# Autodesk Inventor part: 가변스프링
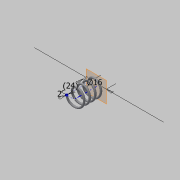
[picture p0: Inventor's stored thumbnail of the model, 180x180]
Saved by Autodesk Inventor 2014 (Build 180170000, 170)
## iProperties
Created: 2015-04
Part Number: 가변스프링
Material: Generic
Document SubType Name: Modeling
Designer: Administrator
Density: 1 g/cm^3
Appearance: Default
Author: Administrator
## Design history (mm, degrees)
sketch "스케치1"
  geometry: L1 (0, 0)-(-8, 0); L2 (-8, 0)-(-8, 11.987); L3 (-8, 11.987)-(0, 11.987); L4 (0, 11.987)-(0, 0); C1 r 1 at (-8, 0)
  constraints: 8 end point, 2 parallel, 1 centre point, 1 coincident, 1 horizontal, 1 perpendicular
  dimensions: "d0" = 16 diameter of L2 L4; "d1" = 11.987 dimension on L3 L1 (derived); "d2" = 2 diameter of C1
feature "코일1" pitch "d3" = 10; turns "d5" = 4; dims "d4" = 11.987 (= d1), "d6" = 0, angle "d7" = 90 deg, angle "d8" = 90 deg, "d9" = 0, "d10" = 0
sketch "스케치2"
  geometry: L1 (7, 0)-(9, 0) reference; 1 further point
  constraints: 1 horizontal alignment
extrude "돌출1" cut sketch "스케치2" stored distance "d11" = 10; taper "d12" = 0 deg
node "작업 평면1"
sketch "스케치3"
  geometry: L1 (-7, 0)-(-9, 0) reference; 1 further point
  constraints: 1 horizontal alignment
extrude "돌출2" cut sketch "스케치3" stored distance "d13" = 10; taper "d14" = 0 deg
node "솔리드1"
node "절단 모서리 투영1"
node "절단 모서리 투영2"
